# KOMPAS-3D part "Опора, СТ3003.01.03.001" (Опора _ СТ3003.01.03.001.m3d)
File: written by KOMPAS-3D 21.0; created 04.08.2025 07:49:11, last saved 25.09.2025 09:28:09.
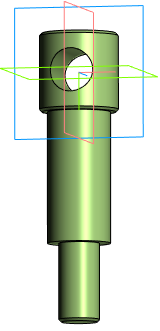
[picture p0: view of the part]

Document properties: Полное имя файла: C:\Users\1\Yandex.Disk\Документы\Новая папка\Стапель №2\Стапель _ СТ3003.00.00.000\Опора _ СТ3003.01.00.000\3D\Струбцина _ СТ3003.01.03.000\Опора _ СТ3003.01.03.001.m3d; Автор: 1

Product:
- Part/product: Опора  | designation СТ3003.01.03.001
    Материал: Круг$d30 ГОСТ 2590-2006;40Х ГОСТ 4543-2016$ (density 7850 kg/m3)
    Масса: 0.339602
    Форматы листов документа: A4

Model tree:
1. Эскиз:1
2. Элемент вращения:1
     Угол 1 = 360
3. Эскиз:2
4. Элемент выдавливания:1
     Расстояние 1 = 35
5. Фаска:1  (with: Элемент вращения:1)  (labels: Круг$d30 ГОСТ 2590-2006;40Х ГОСТ 4543-2016$)
     Угол = 45; Длина 1 = 1; Длина 2 = 1

Expressions: 15.5/2
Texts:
  СТ3003.01.03.001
